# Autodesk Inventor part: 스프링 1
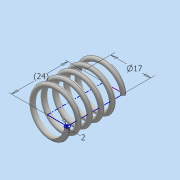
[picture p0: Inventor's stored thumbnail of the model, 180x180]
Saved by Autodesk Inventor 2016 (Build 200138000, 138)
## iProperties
Created: 2019-11
Part Number: 스프링 1
Material: 일반
Document SubType Name: Modeling
Designer: user
Density: 1 g/cm^3
Appearance: 기본값
Mass: 0.818655 g
Surface Area: 16.7049 cm^2
Volume: 0.818655 cm^3
Author: user
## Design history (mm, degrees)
sketch "스케치1"
  geometry: L1 (0, 0)-(8.5, 0); L2 (8.5, 0)-(8.5, 17.5); L3 (8.5, 17.5)-(0, 17.5); L4 (0, 17.5)-(0, 0); C1 r 1 at (8.5, 0)
  constraints: 8 end point, 2 parallel, 1 centre point, 1 coincident, 1 horizontal, 1 perpendicular
  dimensions: "d1" = 17 diameter of L2 L4; "d2" = 2 diameter of C1; "d3" = 17.5 distance of L3.end L1.start (derived)
feature "코일1" sketch "스케치1" pitch "d4" = 10; turns "d6" = 5; dims "d5" = 17.5 (= d3), "d7" = 0, angle "d8" = 90 deg, angle "d9" = 90 deg, "d10" = 0, "d11" = 0
sketch "스케치2"
  geometry: L1 (-15, 17.5)-(15, 17.5); L2 (15, 17.5)-(15, 0); L3 (15, 0)-(-15, 0); L4 (-15, 0)-(-15, 17.5); 2 further points
  constraints: 8 end point, 2 parallel, 1 coincident, 1 horizontal, 1 midpoint, 1 perpendicular
  dimensions: "d12" = 17.5 distance of L3.end L1.start (= d3); "d13" = 30 distance of L1.start L1.end
extrude "돌출1" sketch "스케치2" stored distance "d14" = 117.5; taper "d15" = 0 deg
node "솔리드1"
